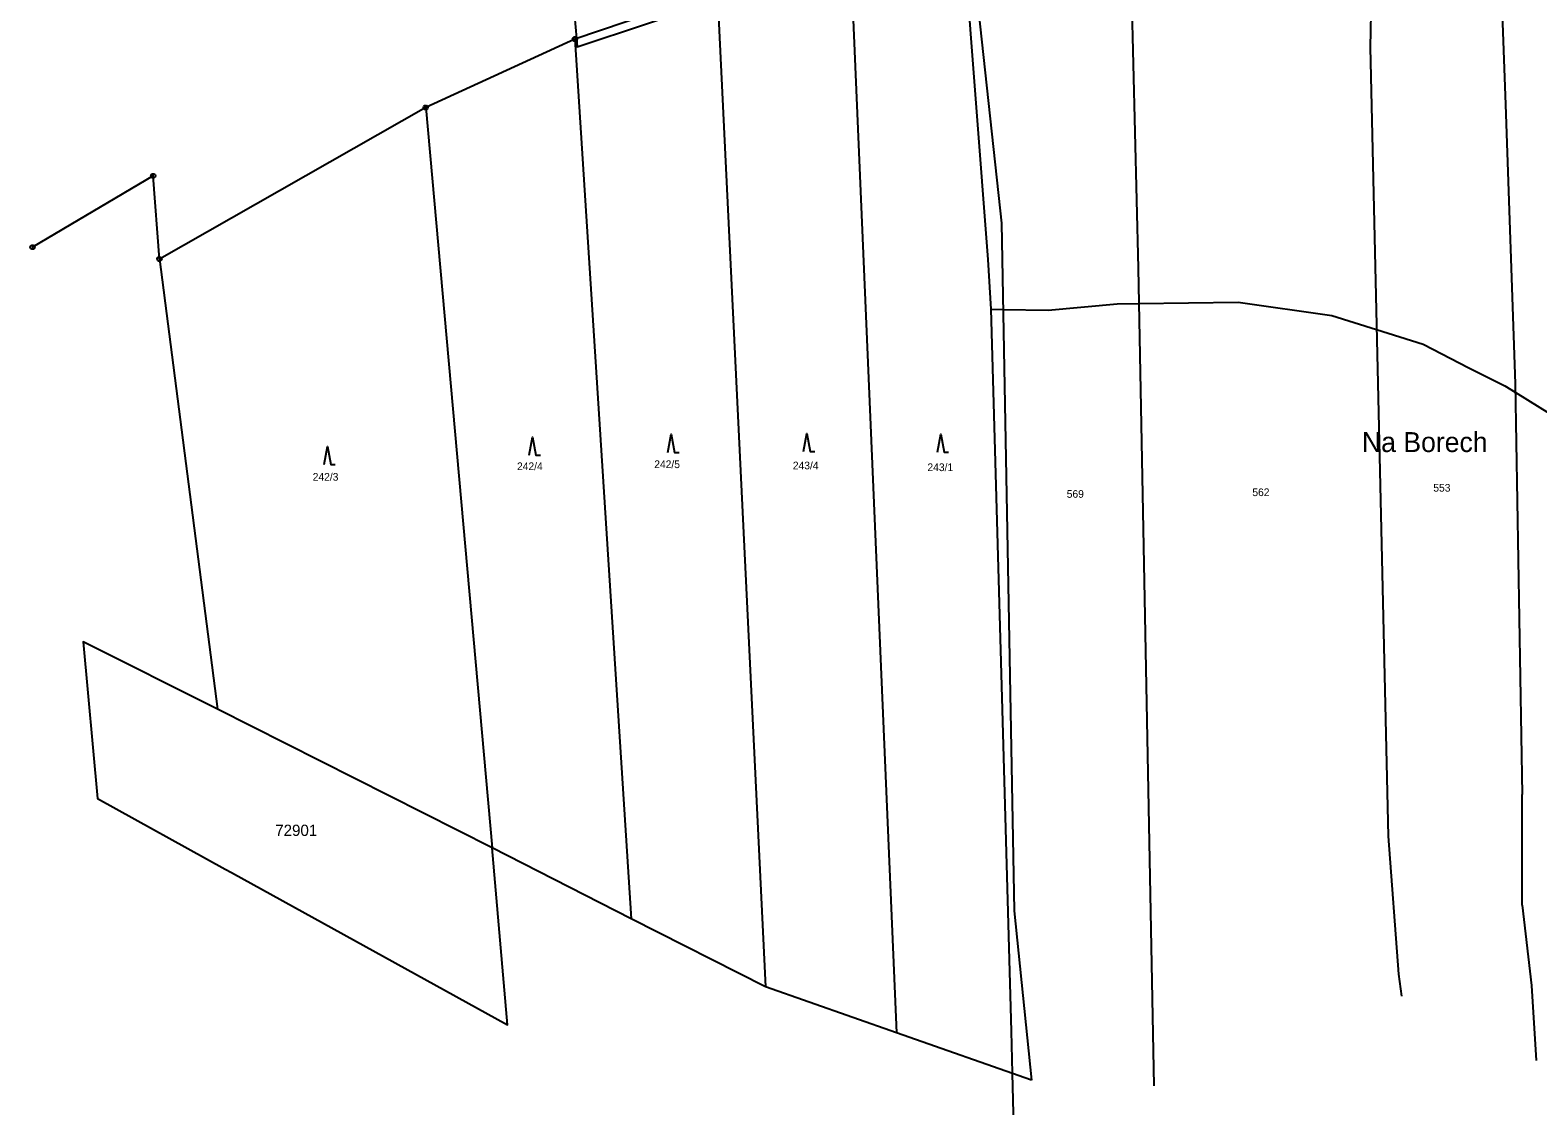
# Model space of a CAD drawing. Extents: x -760978 to -760029, y -1177282 to -1176414.
# Drawn here: x -760946.1 to -760612.3, y -1176974.5 to -1176736.5 of the extents above; entities that cross this region are included whole.
import ezdxf

# ---------------------------------------------------------------- set-up
doc = ezdxf.new("R2010")
doc.units = 0
for name, color, linetype in [('1', 7, 'Continuous'), ('11', 7, 'Continuous'), ('2', 7, 'Continuous'), ('3', 7, 'Continuous'), ('7', 7, 'Continuous'), ('8', 7, 'Continuous')]:
    doc.layers.add(name, color=color, linetype=linetype)

msp = doc.modelspace()

# ---------------------------------------------------------------- linework, layer by layer
at = {"layer": '1'}
for p, q in [((-760648.45, -1176676.85), (-760649.45, -1176740.28)), ((-760622.14, -1176683.02), (-760619.5, -1176752.88)), ((-760703.31, -1176689.19), (-760700.83, -1176789.13)), ((-760738.19, -1176713.51), (-760731.07, -1176779.15)), ((-760764.54, -1176720.19), (-760754.35, -1176958.32)), ((-760794.01, -1176727.76), (-760825.51, -1176738.43)), ((-760794.01, -1176727.76), (-760783.34, -1176948.16)), ((-760825.51, -1176738.43), (-760858.55, -1176753.58)), ((-760825.51, -1176738.43), (-760813.08, -1176933.13)), ((-760649.45, -1176740.28), (-760645.45, -1176914.81)), ((-760858.55, -1176753.58), (-760917.5, -1176787.1)), ((-760858.55, -1176753.58), (-760843.8, -1176917.41)), ((-760619.5, -1176752.88), (-760617.35, -1176814.68)), ((-760918.86, -1176768.7), (-760945.61, -1176784.48)), ((-760917.5, -1176787.1), (-760918.86, -1176768.7)), ((-760731.07, -1176779.15), (-760728.27, -1176931.33)), ((-760917.5, -1176787.1), (-760904.65, -1176886.68)), ((-760700.83, -1176789.13), (-760697.32, -1176970.09)), ((-760617.35, -1176814.68), (-760615.82, -1176905.57)), ((-760843.8, -1176917.41), (-760904.65, -1176886.68)), ((-760615.78, -1176930.06), (-760615.82, -1176905.57)), ((-760645.45, -1176914.81), (-760643.19, -1176945.34)), ((-760813.08, -1176933.13), (-760843.8, -1176917.41)), ((-760728.27, -1176931.33), (-760724.42, -1176968.77)), ((-760615.78, -1176930.06), (-760613.74, -1176947.88)), ((-760783.34, -1176948.16), (-760813.08, -1176933.13)), ((-760643.19, -1176945.34), (-760642.51, -1176950.2)), ((-760754.35, -1176958.32), (-760783.34, -1176948.16)), ((-760613.74, -1176947.88), (-760612.7, -1176964.47)), ((-760724.42, -1176968.77), (-760754.35, -1176958.32))]:
    msp.add_line(p, q, dxfattribs=at)
at = {"layer": '11'}
for points in [[(-760828.93, -1176695.59), (-760825.16, -1176738.31), (-760825, -1176740.14), (-760793.91, -1176729.81)], [(-760739.36, -1176718.88), (-760734.13, -1176787.17), (-760733.46, -1176798.2)], [(-760733.46, -1176798.2), (-760730.72, -1176798.25), (-760720.74, -1176798.43), (-760705.44, -1176797.02), (-760700.68, -1176796.96), (-760678.7, -1176796.68)], [(-760733.46, -1176798.2), (-760731.32, -1176873.64), (-760728.9, -1176957.98), (-760728.68, -1176967.28), (-760727.9, -1177000), (-760727.2, -1177029.34), (-760726.9, -1177042.31), (-760724.48, -1177127.07), (-760723.34, -1177211.81), (-760722.67, -1177217.7)], [(-760678.7, -1176796.68), (-760657.96, -1176799.61), (-760648.02, -1176802.71), (-760637.7, -1176805.92), (-760627.6, -1176811.19), (-760619.61, -1176815.15), (-760617.32, -1176816.58), (-760607.01, -1176823.01)], [(-760843.8, -1176917.41), (-760904.65, -1176886.68), (-760934.37, -1176871.79), (-760931.24, -1176906.51), (-760902.95, -1176922.1), (-760901.56, -1176922.87)], [(-760901.56, -1176922.87), (-760840.43, -1176956.54), (-760843.8, -1176917.41)]]:
    msp.add_lwpolyline(points, dxfattribs=at)
at = {"layer": '3'}
for points in [[(-760774.9, -1176829.72), (-760774.15, -1176825.72), (-760773.4, -1176829.72), (-760772.4, -1176829.72)], [(-760881.06, -1176832.55), (-760880.31, -1176828.55), (-760879.56, -1176832.55), (-760878.56, -1176832.55)], [(-760835.66, -1176830.5), (-760834.91, -1176826.5), (-760834.16, -1176830.5), (-760833.16, -1176830.5)], [(-760804.95, -1176829.88), (-760804.2, -1176825.88), (-760803.45, -1176829.88), (-760802.45, -1176829.88)], [(-760745.28, -1176829.87), (-760744.53, -1176825.87), (-760743.78, -1176829.87), (-760742.78, -1176829.87)]]:
    msp.add_lwpolyline(points, dxfattribs=at)
at = {"layer": '8'}
for p, q in [((-760825.63, -1176738.43), (-760825.39, -1176738.43)), ((-760858.67, -1176753.58), (-760858.43, -1176753.58)), ((-760918.98, -1176768.7), (-760918.74, -1176768.7)), ((-760945.73, -1176784.48), (-760945.49, -1176784.48)), ((-760917.62, -1176787.1), (-760917.38, -1176787.1))]:
    msp.add_line(p, q, dxfattribs=at)
for points in [[(-760825.36, -1176737.95), (-760825.11, -1176738.13), (-760825.01, -1176738.42), (-760825.11, -1176738.71), (-760825.36, -1176738.89), (-760825.67, -1176738.89), (-760825.92, -1176738.71), (-760826.02, -1176738.42), (-760825.92, -1176738.13), (-760825.67, -1176737.95)], [(-760858.4, -1176753.1), (-760858.15, -1176753.28), (-760858.05, -1176753.57), (-760858.15, -1176753.86), (-760858.4, -1176754.04), (-760858.71, -1176754.04), (-760858.96, -1176753.86), (-760859.06, -1176753.57), (-760858.96, -1176753.28), (-760858.71, -1176753.1)], [(-760918.71, -1176768.22), (-760918.46, -1176768.4), (-760918.36, -1176768.69), (-760918.46, -1176768.98), (-760918.71, -1176769.16), (-760919.02, -1176769.16), (-760919.27, -1176768.98), (-760919.37, -1176768.69), (-760919.27, -1176768.4), (-760919.02, -1176768.22)], [(-760945.46, -1176784), (-760945.21, -1176784.18), (-760945.11, -1176784.47), (-760945.21, -1176784.76), (-760945.46, -1176784.94), (-760945.77, -1176784.94), (-760946.02, -1176784.76), (-760946.12, -1176784.47), (-760946.02, -1176784.18), (-760945.77, -1176784)], [(-760917.35, -1176786.62), (-760917.1, -1176786.8), (-760917, -1176787.09), (-760917.1, -1176787.38), (-760917.35, -1176787.56), (-760917.66, -1176787.56), (-760917.91, -1176787.38), (-760918.01, -1176787.09), (-760917.91, -1176786.8), (-760917.66, -1176786.62)]]:
    msp.add_lwpolyline(points, close=True, dxfattribs=at)

# ---------------------------------------------------------------- texts
at = {"layer": '11'}
msp.add_text('72901', height=2.5, dxfattribs=at).set_placement((-760891.86, -1176914.77))
at = {"layer": '2'}
for s, p in [('242/4', (-760838.33, -1176833.81)), ('242/5', (-760807.95, -1176833.36)), ('243/4', (-760777.27, -1176833.64)), ('243/1', (-760747.47, -1176834.03)), ('242/3', (-760883.56, -1176836.15)), ('569', (-760716.63, -1176839.93)), ('562', (-760675.54, -1176839.56)), ('553', (-760635.48, -1176838.57))]:
    msp.add_text(s, height=1.7, dxfattribs=at).set_placement(p)
at = {"layer": '7'}
msp.add_text('Na Borech', height=4.4, dxfattribs=at).set_placement((-760651.27, -1176829.81))

doc.saveas('drawing.dxf')
